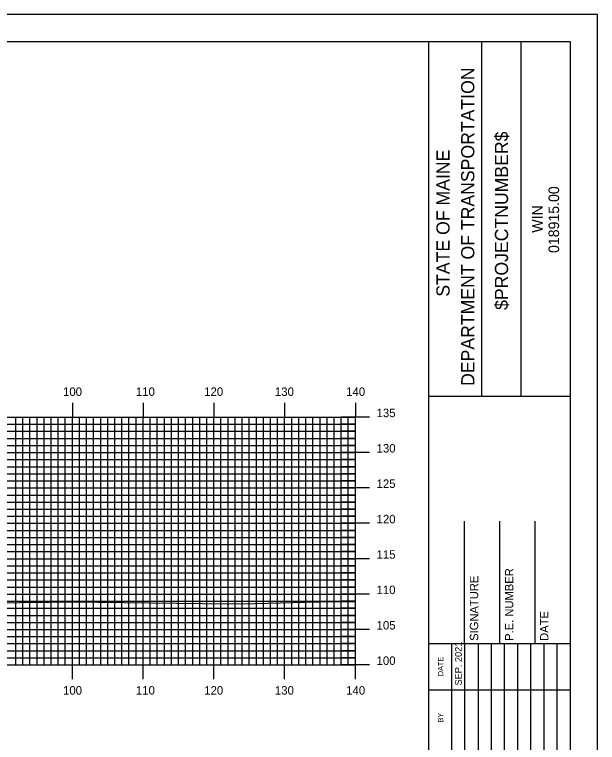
# Model space of a CAD drawing. Extents: x 1781467 to 1781810, y 442591 to 442811.
# Drawn here: x 1781724.2 to 1781806.6, y 442707.7 to 442810.5 of the extents above; entities that cross this region are included whole.
import ezdxf

# ---------------------------------------------------------------- set-up
doc = ezdxf.new("R2010")
doc.units = 0
for name, color, linetype in [('BORDER', 7, 'Continuous'), ('H_V ANNOTATION', 7, 'Continuous'), ('MAJOR', 7, 'Continuous'), ('MINOR', 7, 'Continuous'), ('PLOT BOUNDARY', 7, 'Continuous'), ('S_Roadway_Centerline', 7, 'Continuous')]:
    doc.layers.add(name, color=color, linetype=linetype)

msp = doc.modelspace()

# ---------------------------------------------------------------- linework, layer by layer
at = {"layer": 'BORDER'}
for p, q in [((1781782.81, 442596.67), (1781782.81, 442806.67)), ((1781790.26, 442756.66), (1781790.26, 442806.66)), ((1781795.85, 442756.66), (1781795.85, 442806.66)), ((1781782.81, 442756.65), (1781802.81, 442756.65)), ((1781787.81, 442721.67), (1781787.81, 442738.97)), ((1781792.81, 442721.67), (1781792.81, 442738.97)), ((1781797.81, 442721.67), (1781797.81, 442738.97)), ((1781782.81, 442721.67), (1781802.81, 442721.67))]:
    msp.add_line(p, q, dxfattribs=at)
msp.add_lwpolyline([(1781482.81, 442596.67), (1781802.81, 442596.67), (1781802.81, 442806.67), (1781482.81, 442806.67)], close=True, dxfattribs=at)
for points in [[(1781786.04, 442715.17), (1781786.04, 442721.67)], [(1781787.9, 442686.68), (1781787.9, 442721.67)], [(1781789.77, 442721.67), (1781789.77, 442686.68)], [(1781791.63, 442686.68), (1781791.63, 442721.67)], [(1781793.49, 442686.68), (1781793.49, 442721.67)], [(1781795.36, 442686.68), (1781795.36, 442721.67)], [(1781797.22, 442686.68), (1781797.22, 442721.67)], [(1781799.08, 442686.68), (1781799.08, 442721.67)], [(1781800.95, 442686.68), (1781800.95, 442721.67)], [(1781786.04, 442686.68), (1781786.04, 442720.26)], [(1781782.81, 442715.17), (1781802.81, 442715.17)]]:
    msp.add_lwpolyline(points, dxfattribs=at)
at = {"layer": 'MAJOR'}
for p, q in [((1781732.41, 442755.67), (1781732.41, 442753.67)), ((1781742.41, 442755.67), (1781742.41, 442753.67)), ((1781752.41, 442755.67), (1781752.41, 442753.67)), ((1781762.41, 442755.67), (1781762.41, 442753.67)), ((1781772.41, 442755.67), (1781772.41, 442753.67)), ((1781492.41, 442753.67), (1781772.41, 442753.67)), ((1781492.41, 442753.67), (1781772.41, 442753.67)), ((1781732.41, 442718.67), (1781732.41, 442753.67)), ((1781742.41, 442718.67), (1781742.41, 442753.67)), ((1781752.41, 442718.67), (1781752.41, 442753.67)), ((1781762.41, 442718.67), (1781762.41, 442753.67)), ((1781774.41, 442753.67), (1781770.4, 442753.67)), ((1781772.41, 442718.67), (1781772.41, 442753.67)), ((1781772.41, 442718.67), (1781772.41, 442753.67)), ((1781492.41, 442748.67), (1781772.41, 442748.67)), ((1781774.41, 442748.67), (1781770.4, 442748.67)), ((1781492.41, 442743.67), (1781772.41, 442743.67)), ((1781774.41, 442743.67), (1781770.4, 442743.67)), ((1781492.41, 442738.67), (1781772.41, 442738.67)), ((1781774.41, 442738.67), (1781770.4, 442738.67)), ((1781492.41, 442733.67), (1781772.41, 442733.67)), ((1781774.41, 442733.67), (1781770.4, 442733.67)), ((1781492.41, 442728.67), (1781772.41, 442728.67)), ((1781774.41, 442728.67), (1781770.4, 442728.67)), ((1781492.41, 442723.67), (1781772.41, 442723.67)), ((1781774.41, 442723.67), (1781770.4, 442723.67)), ((1781492.41, 442718.67), (1781772.41, 442718.67)), ((1781492.41, 442718.67), (1781772.41, 442718.67)), ((1781732.41, 442716.66), (1781732.41, 442718.67)), ((1781742.41, 442716.66), (1781742.41, 442718.67)), ((1781752.41, 442716.66), (1781752.41, 442718.67)), ((1781762.41, 442716.66), (1781762.41, 442718.67)), ((1781774.41, 442718.67), (1781770.4, 442718.67)), ((1781772.41, 442716.66), (1781772.41, 442718.67))]:
    msp.add_line(p, q, dxfattribs=at)
at = {"layer": 'MINOR'}
for p, q in [((1781724.41, 442718.67), (1781724.41, 442753.67)), ((1781725.41, 442718.67), (1781725.41, 442753.67)), ((1781726.41, 442718.67), (1781726.41, 442753.67)), ((1781727.41, 442718.67), (1781727.41, 442753.67)), ((1781728.41, 442718.67), (1781728.41, 442753.67)), ((1781729.41, 442718.67), (1781729.41, 442753.67)), ((1781730.41, 442718.67), (1781730.41, 442753.67)), ((1781731.41, 442718.67), (1781731.41, 442753.67)), ((1781733.41, 442718.67), (1781733.41, 442753.67)), ((1781734.41, 442718.67), (1781734.41, 442753.67)), ((1781735.41, 442718.67), (1781735.41, 442753.67)), ((1781736.41, 442718.67), (1781736.41, 442753.67)), ((1781737.41, 442718.67), (1781737.41, 442753.67)), ((1781738.41, 442718.67), (1781738.41, 442753.67)), ((1781739.41, 442718.67), (1781739.41, 442753.67)), ((1781740.41, 442718.67), (1781740.41, 442753.67)), ((1781741.41, 442718.67), (1781741.41, 442753.67)), ((1781743.41, 442718.67), (1781743.41, 442753.67)), ((1781744.41, 442718.67), (1781744.41, 442753.67)), ((1781745.41, 442718.67), (1781745.41, 442753.67)), ((1781746.41, 442718.67), (1781746.41, 442753.67)), ((1781747.41, 442718.67), (1781747.41, 442753.67)), ((1781748.41, 442718.67), (1781748.41, 442753.67)), ((1781749.41, 442718.67), (1781749.41, 442753.67)), ((1781750.41, 442718.67), (1781750.41, 442753.67)), ((1781751.41, 442718.67), (1781751.41, 442753.67)), ((1781753.41, 442718.67), (1781753.41, 442753.67)), ((1781754.41, 442718.67), (1781754.41, 442753.67)), ((1781755.41, 442718.67), (1781755.41, 442753.67)), ((1781756.41, 442718.67), (1781756.41, 442753.67)), ((1781757.41, 442718.67), (1781757.41, 442753.67)), ((1781758.41, 442718.67), (1781758.41, 442753.67)), ((1781759.41, 442718.67), (1781759.41, 442753.67)), ((1781760.41, 442718.67), (1781760.41, 442753.67)), ((1781761.41, 442718.67), (1781761.41, 442753.67)), ((1781763.41, 442718.67), (1781763.41, 442753.67)), ((1781764.41, 442718.67), (1781764.41, 442753.67)), ((1781765.41, 442718.67), (1781765.41, 442753.67)), ((1781766.41, 442718.67), (1781766.41, 442753.67)), ((1781767.41, 442718.67), (1781767.41, 442753.67)), ((1781768.41, 442718.67), (1781768.41, 442753.67)), ((1781769.41, 442718.67), (1781769.41, 442753.67)), ((1781770.41, 442718.67), (1781770.41, 442753.67)), ((1781771.41, 442718.67), (1781771.41, 442753.67)), ((1781492.41, 442752.67), (1781772.41, 442752.67)), ((1781772.41, 442752.67), (1781770.4, 442752.67)), ((1781492.41, 442751.67), (1781772.41, 442751.67)), ((1781772.41, 442751.67), (1781770.4, 442751.67)), ((1781492.41, 442750.67), (1781772.41, 442750.67)), ((1781772.41, 442750.67), (1781770.4, 442750.67)), ((1781492.41, 442749.67), (1781772.41, 442749.67)), ((1781772.41, 442749.67), (1781770.4, 442749.67)), ((1781492.41, 442747.67), (1781772.41, 442747.67)), ((1781772.41, 442747.67), (1781770.4, 442747.67)), ((1781492.41, 442746.67), (1781772.41, 442746.67)), ((1781772.41, 442746.67), (1781770.4, 442746.67)), ((1781492.41, 442745.67), (1781772.41, 442745.67)), ((1781772.41, 442745.67), (1781770.4, 442745.67)), ((1781492.41, 442744.67), (1781772.41, 442744.67)), ((1781772.41, 442744.67), (1781770.4, 442744.67)), ((1781492.41, 442742.67), (1781772.41, 442742.67)), ((1781492.41, 442741.67), (1781772.41, 442741.67)), ((1781772.41, 442742.67), (1781770.4, 442742.67)), ((1781772.41, 442741.67), (1781770.4, 442741.67)), ((1781492.41, 442740.67), (1781772.41, 442740.67)), ((1781772.41, 442740.67), (1781770.4, 442740.67)), ((1781492.41, 442739.67), (1781772.41, 442739.67)), ((1781772.41, 442739.67), (1781770.4, 442739.67)), ((1781492.41, 442737.67), (1781772.41, 442737.67)), ((1781772.41, 442737.67), (1781770.4, 442737.67)), ((1781492.41, 442736.67), (1781772.41, 442736.67)), ((1781772.41, 442736.67), (1781770.4, 442736.67)), ((1781492.41, 442735.67), (1781772.41, 442735.67)), ((1781772.41, 442735.67), (1781770.4, 442735.67)), ((1781492.41, 442734.67), (1781772.41, 442734.67)), ((1781772.41, 442734.67), (1781770.4, 442734.67)), ((1781492.41, 442732.67), (1781772.41, 442732.67)), ((1781772.41, 442732.67), (1781770.4, 442732.67)), ((1781492.41, 442731.67), (1781772.41, 442731.67)), ((1781772.41, 442731.67), (1781770.4, 442731.67)), ((1781492.41, 442730.67), (1781772.41, 442730.67)), ((1781772.41, 442730.67), (1781770.4, 442730.67)), ((1781492.41, 442729.67), (1781772.41, 442729.67)), ((1781772.41, 442729.67), (1781770.4, 442729.67)), ((1781492.41, 442727.67), (1781772.41, 442727.67)), ((1781772.41, 442727.67), (1781770.4, 442727.67)), ((1781492.41, 442726.67), (1781772.41, 442726.67)), ((1781772.41, 442726.67), (1781770.4, 442726.67)), ((1781492.41, 442725.67), (1781772.41, 442725.67)), ((1781772.41, 442725.67), (1781770.4, 442725.67)), ((1781492.41, 442724.67), (1781772.41, 442724.67)), ((1781772.41, 442724.67), (1781770.4, 442724.67)), ((1781492.41, 442722.67), (1781772.41, 442722.67)), ((1781772.41, 442722.67), (1781770.4, 442722.67)), ((1781492.41, 442721.67), (1781772.41, 442721.67)), ((1781772.41, 442721.67), (1781770.4, 442721.67)), ((1781492.41, 442720.67), (1781772.41, 442720.67)), ((1781772.41, 442720.67), (1781770.4, 442720.67)), ((1781492.41, 442719.67), (1781772.41, 442719.67)), ((1781772.41, 442719.67), (1781770.4, 442719.67))]:
    msp.add_line(p, q, dxfattribs=at)
at = {"layer": 'PLOT BOUNDARY'}
msp.add_lwpolyline([(1781466.62, 442590.55), (1781806.62, 442590.55), (1781806.62, 442810.55), (1781466.62, 442810.55)], close=True, dxfattribs=at)
at = {"layer": 'S_Roadway_Centerline'}
msp.add_lwpolyline([(1781593.87, 442727.96), (1781606.48, 442727.73), (1781617.86, 442727.47), (1781620.12, 442727.44), (1781641.46, 442727.3), (1781641.85, 442727.29), (1781642.28, 442727.3), (1781664.58, 442727.45), (1781665.29, 442727.46), (1781676.24, 442727.38), (1781688.68, 442727.78), (1781690.56, 442727.77), (1781710.17, 442727.27), (1781711.23, 442727.28), (1781712.29, 442727.33), (1781733.34, 442727.58), (1781736.01, 442727.52), (1781754.54, 442727.3), (1781758.15, 442727.36), (1781769.13, 442727.64), (1781772.41, 442727.64)], dxfattribs=at)

# ---------------------------------------------------------------- texts
at = {"layer": 'BORDER'}
for s, height, p in [('DEPARTMENT OF TRANSPORTATION', 1.8635, (1781789.22, 442758.08)), ('$PROJECTNUMBER$', 1.8635, (1781793.99, 442768.82)), ('STATE OF MAINE', 1.8635, (1781785.72, 442770.69)), ('018915.00', 1.491, (1781801.2, 442776.86)), ('WIN', 1.491, (1781798.88, 442779.73)), ('P.E. NUMBER', 1.1811, (1781794.73, 442722.06)), ('SIGNATURE', 1.181, (1781789.77, 442722.06)), ('DATE', 1.181, (1781799.69, 442722.06)), ('SEP. 2021', 0.969, (1781787.45, 442715.76)), ('DATE', 0.743, (1781784.82, 442717.08)), ('BY', 0.743, (1781784.82, 442710.54))]:
    msp.add_text(s, height=height, rotation=90, dxfattribs=at).set_placement(p)
at = {"layer": 'H_V ANNOTATION'}
for s, p in [('100', (1781731.09, 442756.67)), ('110', (1781741.39, 442756.67)), ('120', (1781751.05, 442756.67)), ('130', (1781761.04, 442756.67)), ('140', (1781771.11, 442756.67)), ('135', (1781775.41, 442753.67)), ('130', (1781775.41, 442748.67)), ('125', (1781775.41, 442743.67)), ('120', (1781775.41, 442738.67)), ('115', (1781775.41, 442733.67)), ('110', (1781775.41, 442728.67)), ('105', (1781775.41, 442723.67)), ('100', (1781775.41, 442718.67)), ('100', (1781731.09, 442714.47)), ('110', (1781741.39, 442714.47)), ('120', (1781751.05, 442714.47)), ('130', (1781761.04, 442714.47)), ('140', (1781771.11, 442714.47))]:
    msp.add_text(s, height=1.2, dxfattribs=at).set_placement(p)

doc.saveas('drawing.dxf')
